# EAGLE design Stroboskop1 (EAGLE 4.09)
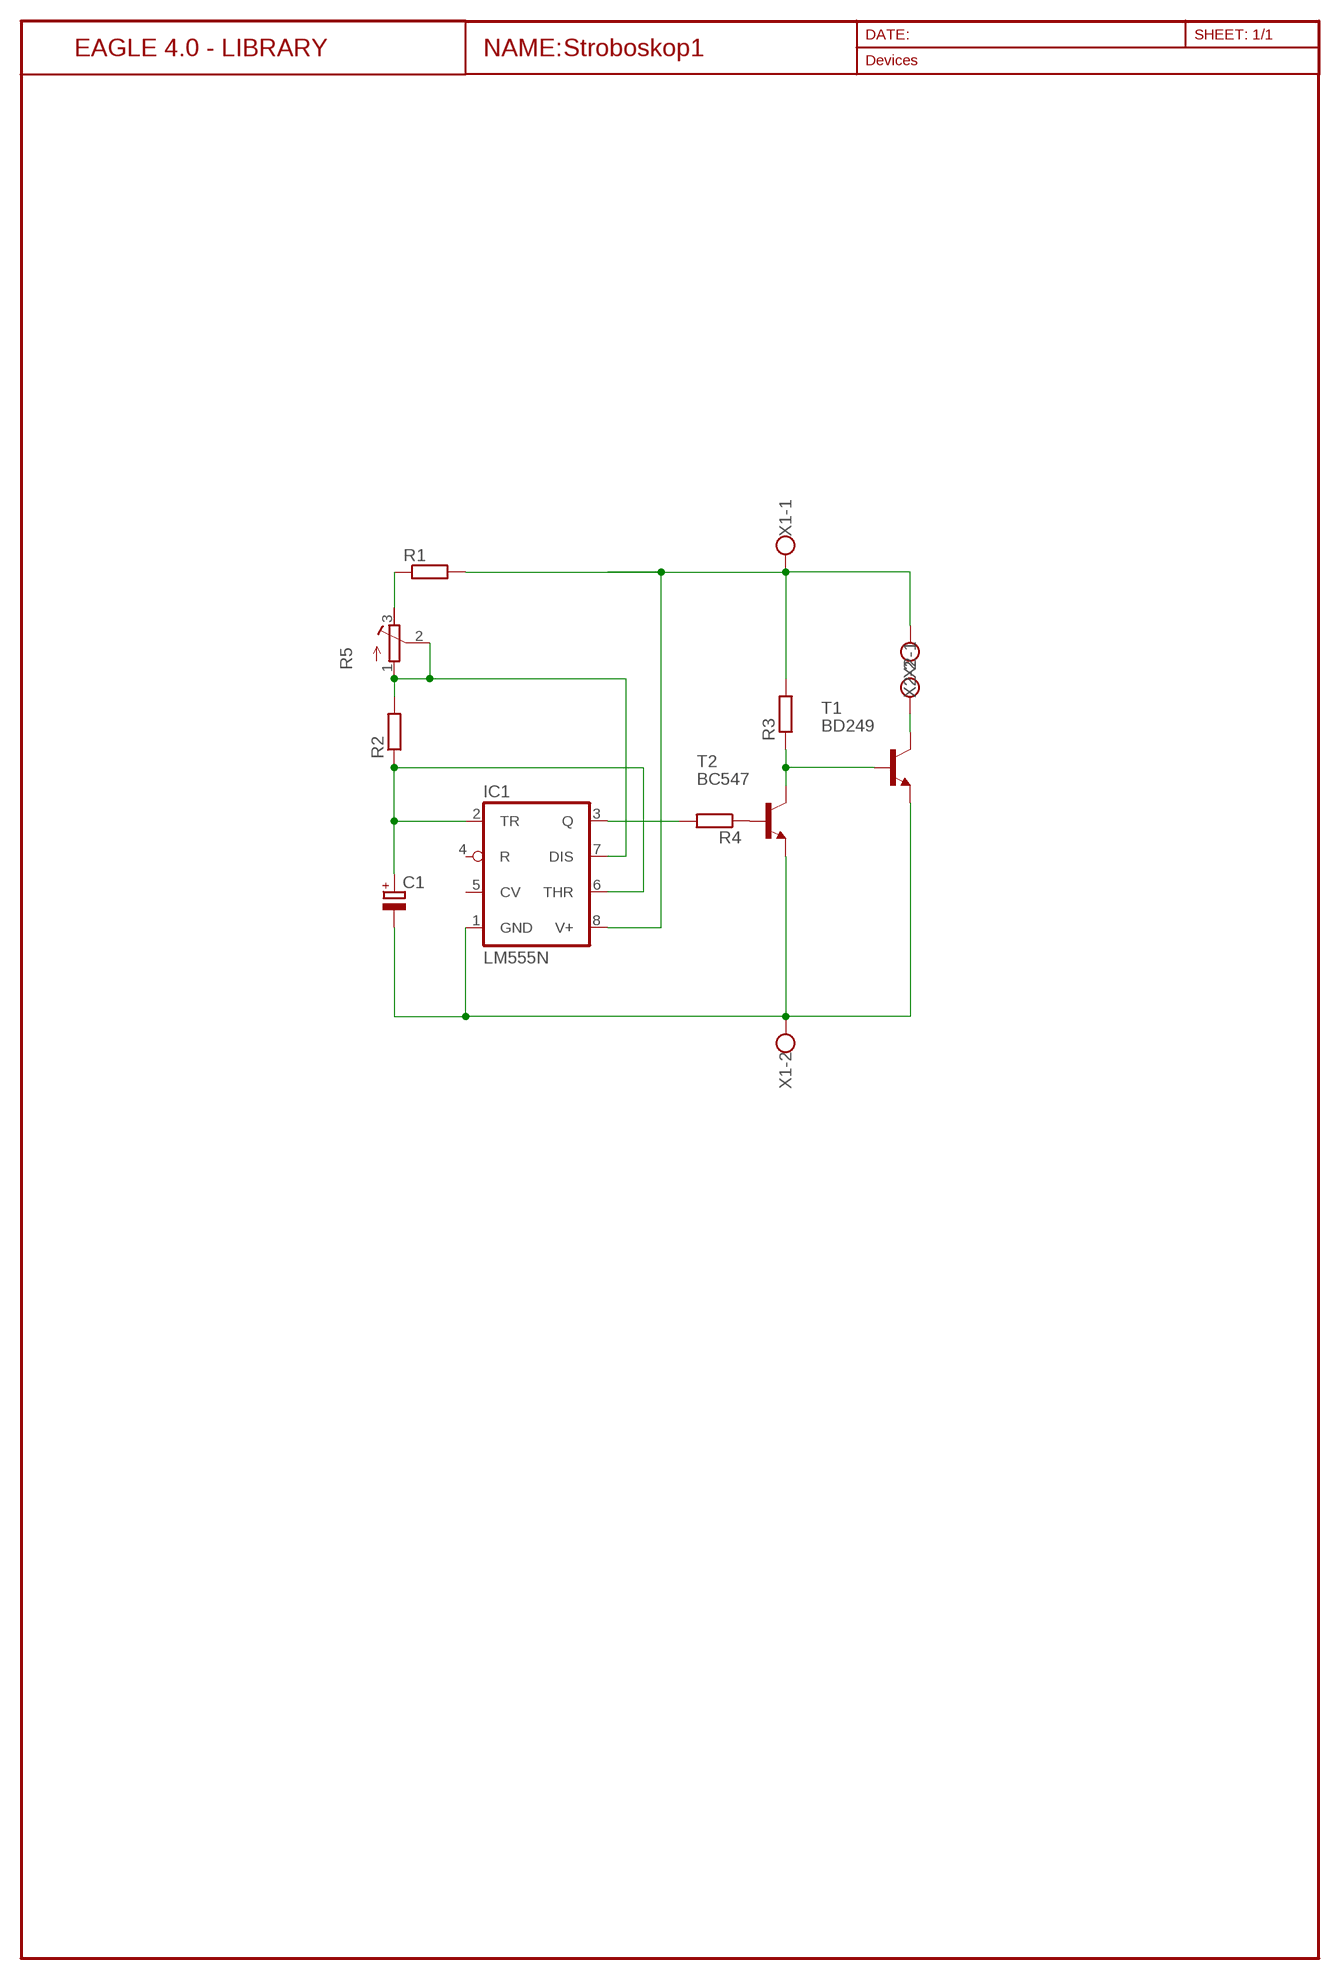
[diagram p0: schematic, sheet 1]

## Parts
C1  CPOL-EUE5-13  [E5-13]
IC1  LM555N  [DIL08]
R1  R-EU_0204/7  [0204/7]
R2  R-EU_0204/7  [0204/7]
R3  R-EU_0204/7  [0204/7]
R4  R-EU_0204/7  [0204/7]
R5  R-TRIMM3339P  [RTRIM3339P]
T1  BD249  [TOP3]
T2  BC547  [TO92-]
X1  W237-102  [W237-102]
X2  W237-102  [W237-102]

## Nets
N$2: C1.+ IC1.2(TR) IC1.6(THR) R2.1
N$3: IC1.8(V+) R1.2 R3.2 X1.1 X2.2
N$4: R3.1 T1.1(B) T2.3(C)
N$5: T1.2(C) X2.1
N$6: R4.1 T2.2(B)
N$7: IC1.3(Q) R4.2
N$8: IC1.7(DIS) R2.2 R5.1(E) R5.2(S)
N$9: C1.- IC1.1(GND) T1.3(E) T2.1(E) X1.2
N$11: R1.1 R5.3(A)
Unconnected: IC1.4(R) IC1.5(CV)

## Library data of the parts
C1 = Standartni Soucastky 1:CPOL-EU: POLARIZED CAPACITOR, European symbol
IC1 = Standartni Soucastky 3:*555: TIMER
R1-R4 = Standartni Soucastky 1:R-EU_: RESISTOR, European symbol
R5 = Standartni Soucastky 1:R-TRIMM: Trimm resistor
T1 = Tranzistory - NPN:BD249: NPN TRANSISTOR
T2 = Tranzistory - NPN:BC547: NPN TRANSISTOR
X1 X2 = Konektory - Wago 2:W237-102: WAGO SCREW CLAMP

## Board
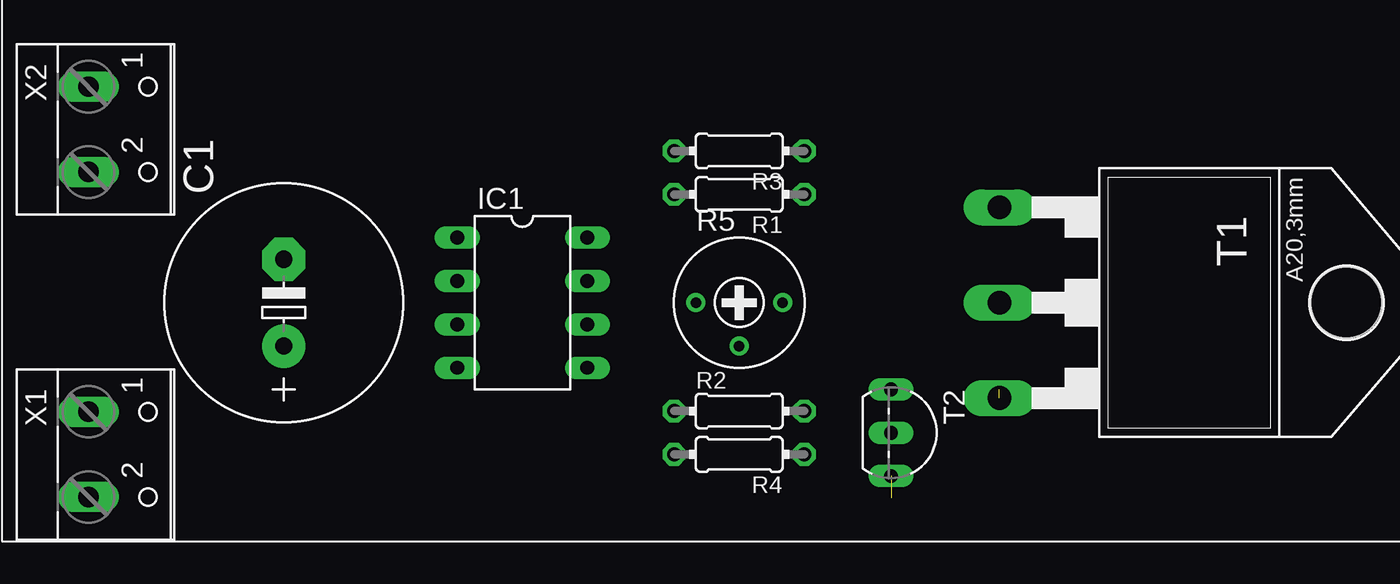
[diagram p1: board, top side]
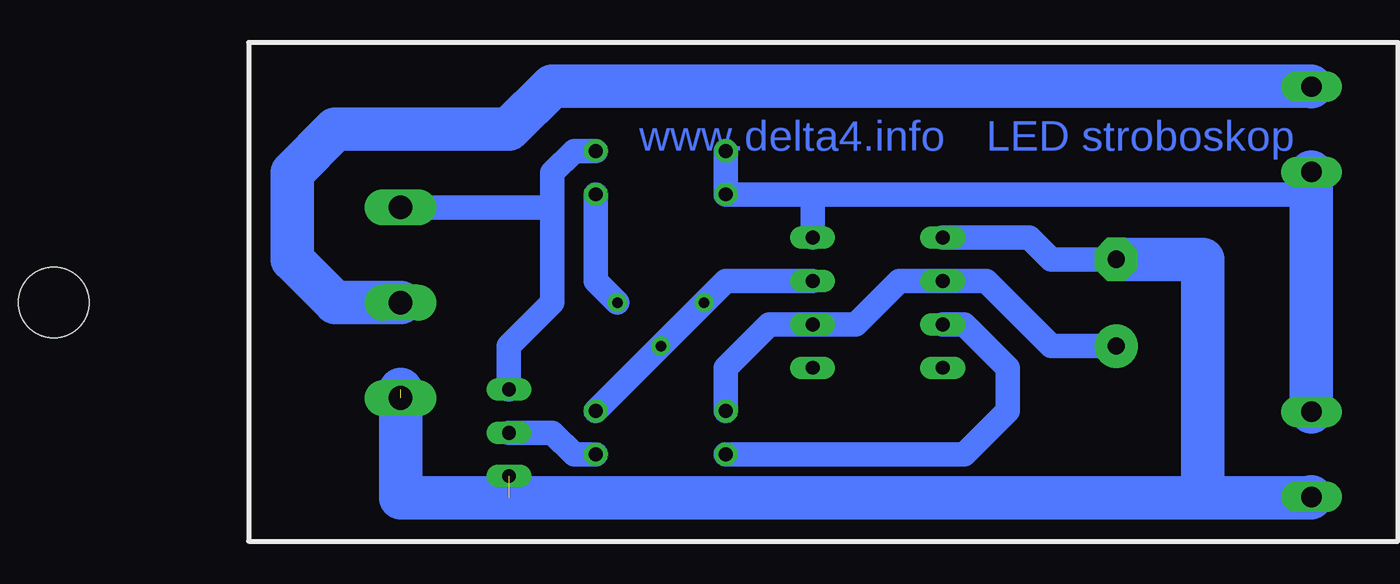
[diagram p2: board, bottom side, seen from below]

No outline drawn. Coordinates in mm, seen from the top.
Copper layers 16: Bottom 0.035mm
Design rules "default": minimum track width 10mil, minimum drill 24mil, track to track 8mil, track to pad 8mil, pad to pad 8mil, via to via 8mil, smd to smd 8mil, copper to edge 40mil, drill to drill 8mil, minimum pad ring 10mil, minimum via ring 8mil, stop-mask expansion 4mil, vias tented up to drill 0mil, thermal gap 10mil

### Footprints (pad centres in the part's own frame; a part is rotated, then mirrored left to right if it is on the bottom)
E5-13 = drill 1.016 pad 2.54 round: + -2.54,0 | drill 1.016 pad 2.54 octagon: - 2.54,0
DIL08 = drill 0.813 long: 1 -3.81,-3.81; 2 -1.27,-3.81; 3 1.27,-3.81; 4 3.81,-3.81; 5 3.81,3.81; 6 1.27,3.81; 7 -1.27,3.81; 8 -3.81,3.81
0204/7 = drill 0.813 octagon: 1 -3.81,0; 2 3.81,0
RTRIM3339P = drill 0.61 round: 1 -2.54,0; 2 0,-2.54; 3 2.54,0
TOP3 = drill 1.397 long: 1 -5.588,-7.62; 2 0,-7.62; 3 5.588,-7.62 | hole 4.115: 0,12.7
TO92- = drill 0.813 long: 1 2.54,-1.27; 2 0,-1.27; 3 -2.54,-1.27
W237-102 = drill 1.194 long: 1 -2.5,-1.27; 2 2.5,-1.27

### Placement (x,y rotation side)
C1  19.05,13.97 90 top
IC1  33.02,13.97 270 top
R1  45.72,20.32 180 top
R2  45.72,7.62 0 top
R3  45.72,22.86 180 top
R4  45.72,5.08 180 top
R5  45.72,13.97 0 top
T1  68.58,13.97 270 top
T2  55.88,6.35 270 top
U$1  [100X60]  2.54,0 0 top
X1  8.89,5.08 270 top
X2  8.89,24.13 270 top

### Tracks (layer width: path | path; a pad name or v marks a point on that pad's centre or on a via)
N$2
  Bottom 1.422: R2.1 41.91,10.16 39.37,12.7 IC1.6 34.29,12.7 31.75,15.24 IC1.2 26.67,15.24 22.86,11.43 C1.+
N$3
  Bottom 1.422: 36.83,20.32 IC1.8 | 36.83,20.32 R1.2 R3.2 | 7.62,20.32 36.83,20.32
  Bottom 2.54: X1.1 7.62,20.32 X2.2
N$4
  Bottom 1.422: T2.3 54.61,11.43 52.07,13.97 52.07,19.56 | R3.1 50.8,22.86 52.07,21.59 52.07,19.56 | T1.1 52.07,19.56
N$5
  Bottom 2.54: X2.1 7.66,26.67 52.07,26.67 54.61,24.13 64.77,24.13 67.31,21.59 67.31,16.51 64.77,13.97 T1.2
N$6
  Bottom 1.422: T2.2 52.07,6.35 50.8,5.08 R4.1
N$7
  Bottom 1.422: IC1.3 27.94,12.7 25.4,10.16 25.4,7.62 27.94,5.08 R4.2
N$8
  Bottom 1.422: IC1.7 41.91,15.24 R5.1 R5.2 R2.2
N$9  (2 unrouted)
  Bottom 1.422: IC1.1 24.13,17.78 22.86,16.51 C1.-
  Bottom 2.54: X1.2 7.66,2.54 13.97,2.54 | 13.97,2.54 54.61,2.54 60.96,2.54 60.96,8.89 | 13.97,2.54 13.97,16.51 C1.-
N$11
  Bottom 1.422: R5.3 49.53,15.24 R1.1

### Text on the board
Bottom: LED stroboskop | www.delta4.info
